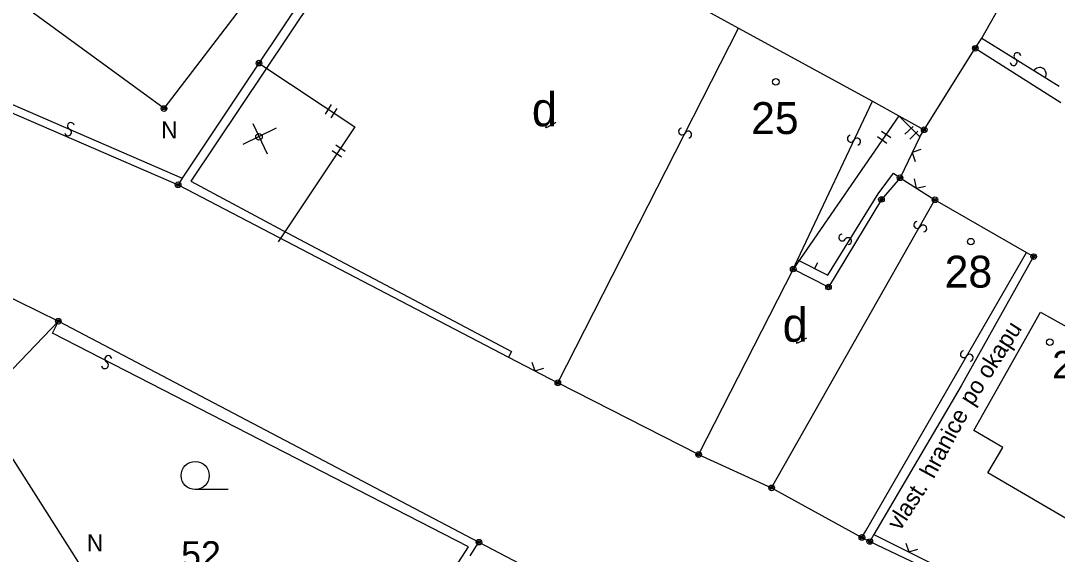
# Model space of a CAD drawing. Extents: x -815878 to -812162, y -1076286 to -1072327.
# Drawn here: x -813365.2 to -813310, y -1074319.7 to -1074291.3 of the extents above; entities that cross this region are included whole.
import ezdxf

# ---------------------------------------------------------------- set-up
doc = ezdxf.new("R2010")
doc.units = 0
for name, color, linetype in [('Vrstva 1', 7, 'Continuous'), ('Vrstva 18', 7, 'Continuous'), ('Vrstva 19', 7, 'Continuous'), ('Vrstva 24', 7, 'Continuous'), ('Vrstva 25', 7, 'Continuous'), ('Vrstva 39', 7, 'Continuous'), ('Vrstva 4', 7, 'Continuous'), ('Vrstva 56', 7, 'Continuous'), ('Vrstva 62', 7, 'Continuous')]:
    doc.layers.add(name, color=color, linetype=linetype)

msp = doc.modelspace()

# ---------------------------------------------------------------- linework, layer by layer
at = {"layer": 'Vrstva 1'}
for p, q in [((-813344.8, -1074281.93), (-813352.53, -1074293.55)), ((-813357.59, -1074295.97), (-813349.6, -1074285.55)), ((-813314.03, -1074292.22), (-813312.56, -1074289.64)), ((-813357.59, -1074295.97), (-813364.93, -1074290.61)), ((-813314.37, -1074292.76), (-813314.03, -1074292.22)), ((-813317.09, -1074297.1), (-813314.37, -1074292.76)), ((-813314.37, -1074292.76), (-813309.81, -1074295.65)), ((-813352.53, -1074293.55), (-813356.62, -1074299.68)), ((-813365.85, -1074296.12), (-813356.84, -1074300.03)), ((-813317.33, -1074297.48), (-813318.38, -1074299.66)), ((-813317.33, -1074297.48), (-813317.09, -1074297.1)), ((-813356.62, -1074299.68), (-813356.84, -1074300.03)), ((-813318.38, -1074299.66), (-813319.37, -1074300.81)), ((-813318.38, -1074299.66), (-813316.52, -1074300.83)), ((-813356.84, -1074300.03), (-813339.24, -1074309.22)), ((-813319.37, -1074300.81), (-813322.19, -1074305.48)), ((-813316.52, -1074300.83), (-813311.64, -1074303.64)), ((-813374.5, -1074301.73), (-813363.22, -1074307.3)), ((-813311.64, -1074303.64), (-813311.26, -1074303.86)), ((-813311.26, -1074303.86), (-813315.13, -1074310.74)), ((-813324.07, -1074304.52), (-813329.11, -1074314.4)), ((-813322.19, -1074305.48), (-813324.07, -1074304.52)), ((-813314.45, -1074313.12), (-813310.89, -1074306.81)), ((-813310.89, -1074306.81), (-813309.33, -1074307.69)), ((-813363.22, -1074307.3), (-813367.49, -1074311.76)), ((-813363.22, -1074307.3), (-813340.81, -1074319.07)), ((-813339.24, -1074309.22), (-813336.61, -1074310.58)), ((-813329.11, -1074314.4), (-813336.61, -1074310.58)), ((-813315.13, -1074310.74), (-813319.78, -1074318.66)), ((-813367.49, -1074311.76), (-813361.92, -1074320.52)), ((-813312.91, -1074314.03), (-813314.45, -1074313.12)), ((-813313.7, -1074315.37), (-813312.91, -1074314.03)), ((-813329.11, -1074314.4), (-813325.22, -1074316.18)), ((-813306.37, -1074319.67), (-813313.7, -1074315.37)), ((-813325.22, -1074316.18), (-813320.41, -1074318.82)), ((-813341.28, -1074319.79), (-813340.81, -1074319.07)), ((-813320.41, -1074318.82), (-813319.99, -1074319.04)), ((-813319.78, -1074318.66), (-813319.99, -1074319.04)), ((-813319.99, -1074319.04), (-813316.36, -1074320.75))]:
    msp.add_line(p, q, dxfattribs=at)
at = {"layer": 'Vrstva 24'}
for centre, radius in [((-813314.37, -1074292.76), 0.15), ((-813314.37, -1074292.76), 0.075), ((-813352.53, -1074293.55), 0.15), ((-813352.53, -1074293.55), 0.075), ((-813357.59, -1074295.97), 0.15), ((-813357.59, -1074295.97), 0.075), ((-813317.09, -1074297.1), 0.15), ((-813317.09, -1074297.1), 0.075), ((-813318.38, -1074299.66), 0.15), ((-813318.38, -1074299.66), 0.075), ((-813356.84, -1074300.03), 0.15), ((-813356.84, -1074300.03), 0.075), ((-813319.37, -1074300.81), 0.15), ((-813319.37, -1074300.81), 0.075), ((-813316.52, -1074300.83), 0.15), ((-813316.52, -1074300.83), 0.075), ((-813311.26, -1074303.86), 0.15), ((-813311.26, -1074303.86), 0.075), ((-813324.07, -1074304.52), 0.15), ((-813324.07, -1074304.52), 0.075), ((-813322.19, -1074305.48), 0.15), ((-813322.19, -1074305.48), 0.075), ((-813363.22, -1074307.3), 0.15), ((-813363.22, -1074307.3), 0.075), ((-813336.61, -1074310.58), 0.15), ((-813336.61, -1074310.58), 0.075), ((-813329.11, -1074314.4), 0.15), ((-813329.11, -1074314.4), 0.075), ((-813325.22, -1074316.18), 0.15), ((-813325.22, -1074316.18), 0.075), ((-813340.81, -1074319.07), 0.15), ((-813340.81, -1074319.07), 0.075), ((-813320.41, -1074318.82), 0.15), ((-813320.41, -1074318.82), 0.075), ((-813319.99, -1074319.04), 0.15), ((-813319.99, -1074319.04), 0.075)]:
    msp.add_circle(centre, radius, dxfattribs=at)
at = {"layer": 'Vrstva 25'}
msp.add_line((-813354.18, -1074316.27), (-813355.93, -1074316.27), dxfattribs=at)
for centre, radius in [((-813325, -1074294.55), 0.175), ((-813352.53, -1074297.48), 0.175), ((-813314.61, -1074303.06), 0.175), ((-813310.4, -1074308.42), 0.175), ((-813355.93, -1074315.52), 0.75)]:
    msp.add_circle(centre, radius, dxfattribs=at)
for points in [[(-813337.242, -1074296.913), (-813337.242, -1074296.93), (-813337.281, -1074297.038), (-813336.711, -1074296.701)], [(-813323.882, -1074308.393), (-813323.882, -1074308.41), (-813323.921, -1074308.518), (-813323.351, -1074308.181)]]:
    msp.add_open_spline(points, degree=2, dxfattribs=at)
at = {"layer": 'Vrstva 39'}
for p, q in [((-813353.37, -1074297.86), (-813351.6, -1074297)), ((-813352.85, -1074296.77), (-813352.09, -1074298.39))]:
    msp.add_line(p, q, dxfattribs=at)
at = {"layer": 'Vrstva 4'}
for p, q in [((-813344.35, -1074282.18), (-813356.17, -1074299.84)), ((-813332.63, -1074288.59), (-813326.98, -1074291.68)), ((-813336.61, -1074310.58), (-813326.98, -1074291.68)), ((-813326.98, -1074291.68), (-813319.85, -1074295.57)), ((-813314.03, -1074292.22), (-813309.9, -1074294.78)), ((-813352.53, -1074293.55), (-813347.43, -1074296.94)), ((-813365.67, -1074295.75), (-813356.62, -1074299.68)), ((-813323.85, -1074304.03), (-813319.85, -1074295.57)), ((-813319.85, -1074295.57), (-813318.44, -1074296.35)), ((-813318.44, -1074296.35), (-813324.07, -1074304.52)), ((-813318.44, -1074296.35), (-813317.33, -1074297.48)), ((-813318.44, -1074296.35), (-813317.09, -1074297.1)), ((-813347.43, -1074296.94), (-813351.51, -1074303.07)), ((-813319.54, -1074300.51), (-813318.73, -1074299.42)), ((-813318.73, -1074299.42), (-813318.38, -1074299.66)), ((-813356.17, -1074299.84), (-813350.99, -1074302.61)), ((-813325.22, -1074316.18), (-813316.52, -1074300.83)), ((-813322.23, -1074304.85), (-813319.54, -1074300.51)), ((-813350.99, -1074302.61), (-813339.07, -1074308.92)), ((-813320.2, -1074318.46), (-813311.64, -1074303.64)), ((-813324.07, -1074304.52), (-813323.85, -1074304.03)), ((-813323.85, -1074304.03), (-813322.23, -1074304.85)), ((-813324.07, -1074304.52), (-813324.07, -1074304.52)), ((-813363.53, -1074307.94), (-813363.22, -1074307.3)), ((-813341.36, -1074319.32), (-813363.53, -1074307.94)), ((-813339.07, -1074308.92), (-813339.24, -1074309.22)), ((-813320.41, -1074318.82), (-813320.2, -1074318.46)), ((-813340.81, -1074319.07), (-813336.94, -1074321.1)), ((-813319.78, -1074318.66), (-813316.19, -1074320.45)), ((-813346.8, -1074327.69), (-813341.36, -1074319.32))]:
    msp.add_line(p, q, dxfattribs=at)
at = {"layer": 'Vrstva 62'}
for p, q in [((-813348.994, -1074296.261), (-813348.662, -1074295.761)), ((-813348.694, -1074296.46), (-813348.362, -1074295.96)), ((-813318.116, -1074297.342), (-813317.688, -1074296.922)), ((-813319.573, -1074297.465), (-813319.079, -1074297.806)), ((-813319.369, -1074297.169), (-813318.875, -1074297.509)), ((-813317.863, -1074297.599), (-813317.435, -1074297.178)), ((-813348.433, -1074297.905), (-813347.933, -1074298.238)), ((-813317.265, -1074298.154), (-813317.734, -1074298.319)), ((-813348.632, -1074298.205), (-813348.133, -1074298.537)), ((-813317.734, -1074298.319), (-813317.571, -1074298.789)), ((-813317.623, -1074299.722), (-813317.511, -1074300.207)), ((-813317.511, -1074300.207), (-813317.026, -1074300.098)), ((-813322.77, -1074304.184), (-813322.929, -1074304.496)), ((-813337.988, -1074309.473), (-813337.836, -1074309.946)), ((-813337.836, -1074309.946), (-813337.362, -1074309.797)), ((-813318.066, -1074319.123), (-813317.907, -1074319.594)), ((-813317.907, -1074319.594), (-813317.435, -1074319.438))]:
    msp.add_line(p, q, dxfattribs=at)
for centre, radius, start, end in [((-813312.131, -1074293.18), 0.184, 5.3654, 237.9554), ((-813312.327, -1074293.492), 0.184, 185.5798, 57.6778), ((-813310.94, -1074294.135), 0.35, 328.4531, 147.9611), ((-813362.704, -1074297.239), 0.184, 193.8996, 65.9976), ((-813362.555, -1074296.902), 0.184, 13.6852, 246.2752), ((-813329.994, -1074297.191), 0.184, 100.1584, 332.7484), ((-813329.667, -1074297.36), 0.184, 280.3728, 152.4708), ((-813320.999, -1074297.575), 0.184, 101.914, 334.504), ((-813320.667, -1074297.734), 0.184, 282.1285, 154.2265), ((-813317.459, -1074302.176), 0.184, 97.6148, 330.2048), ((-813317.14, -1074302.36), 0.184, 277.8292, 149.9272), ((-813321.46, -1074302.84), 0.184, 95.367, 327.957), ((-813321.148, -1074303.036), 0.184, 275.5815, 147.6794), ((-813360.559, -1074309.318), 0.184, 9.2678, 241.3658), ((-813314.981, -1074309.056), 0.184, 97.1418, 329.7318), ((-813314.664, -1074309.242), 0.184, 277.3563, 149.4542), ((-813360.735, -1074309.642), 0.184, 189.0533, 61.6433)]:
    msp.add_arc(centre, radius, start, end, dxfattribs=at)

# ---------------------------------------------------------------- texts
at = {"layer": 'Vrstva 18'}
msp.add_text('52', height=1.4276, dxfattribs=at).set_placement((-813356.682, -1074320.448))
at = {"layer": 'Vrstva 19'}
for s, height, p in [('25', 1.7, (-813326.311, -1074297.33)), ('28', 1.7, (-813316.001, -1074305.51)), ('29/2', 1.4514, (-813310.267, -1074310.335))]:
    msp.add_text(s, height=height, dxfattribs=at).set_placement(p)
at = {"layer": 'Vrstva 25'}
for p in [(-813337.993, -1074296.912), (-813324.633, -1074308.392)]:
    msp.add_text('d', height=1.8, dxfattribs=at).set_placement(p)
at = {"layer": 'Vrstva 56'}
for p in [(-813357.74, -1074297.56), (-813361.7, -1074319.56)]:
    msp.add_text('N', height=0.9, dxfattribs=at).set_placement(p)
for s, rotation, p in [('po okapu', 57.3869, (-813314.52, -1074311.85)), ('hranice', 61.5703, (-813316.589, -1074315.734)), ('vlast.', 57.0282, (-813318.382, -1074318.508))]:
    msp.add_text(s, height=0.9, rotation=rotation, dxfattribs=at).set_placement(p)

doc.saveas('drawing.dxf')
